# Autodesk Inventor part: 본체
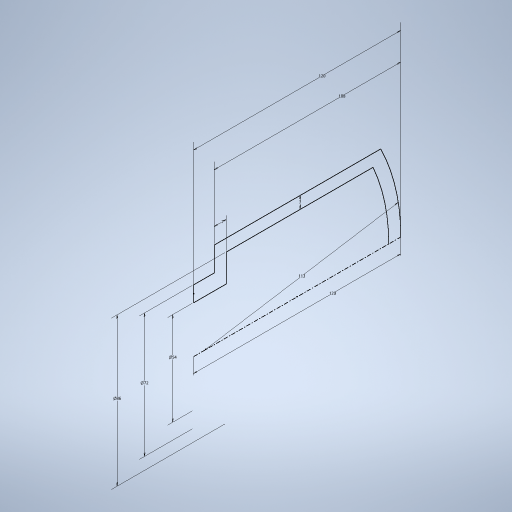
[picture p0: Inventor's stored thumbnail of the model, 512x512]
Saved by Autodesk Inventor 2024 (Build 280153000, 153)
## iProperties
Created: 2023-08
Part Number: 본체
Material: 일반
Document SubType Name: Modeling
Designer: Owner
Density: 1 g/cm^3
Appearance: 기본값
Author: Owner
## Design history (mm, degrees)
sketch "스케치1"
  geometry: L1 (0, 60)-(0, -60); L2 (27, 60)-(36, 60); L3 (36, 60)-(36, 48); L4 (36, 48)-(50, 48); L5 (50, 48)-(50, -48.336); L6 (43, -43.887)-(43, 41); L7 (43, 41)-(27, 41); L8 (27, 41)-(27, 60); A1 r 113 centre (0, 53) between (0, -60) and (50, -48.336); A2 r 106 centre (0, 53) between (0, -53) and (43, -43.887); 3 further points
  constraints: 16 end point, 4 point on circle, 3 perpendicular, 2 centre point, 2 horizontal, 2 midpoint, 2 point on line, 1 coincident, 1 vertical, 1 other
  dimensions: "d0" = 120 distance of L1.start L1.end; "d1" = 113 radius of A1; "d2" = 7 distance between parallel lines of L5 L6; "d3" = 120 vertical distance of L1.end point (31.5, 60); "d4" = 108 vertical distance of L1.end L4.end; "d5" = 7 distance between parallel lines of L4 L7; "d6" = 54 diameter of L8 L1; "d8" = 72 diameter of L3 L1; "d9" = 86 diameter of L6 L1
